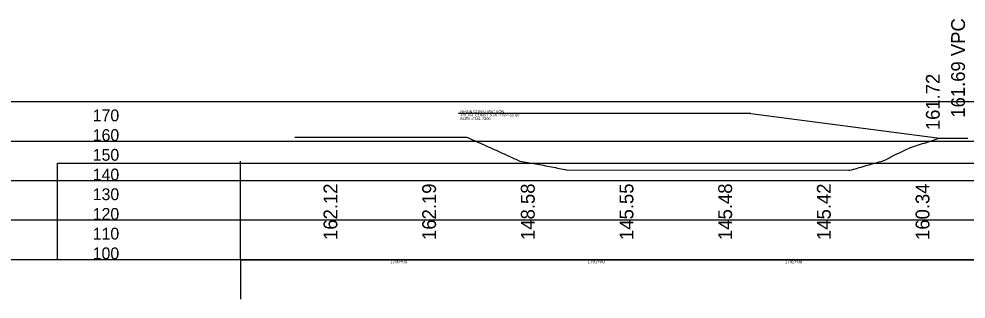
# Model space of a CAD drawing. Extents: x 2126510 to 2136144, y 865066 to 868066.
# Drawn here: x 2127256.4 to 2127736.3, y 866593.9 to 866736 of the extents above; entities that cross this region are included whole.
import ezdxf

# ---------------------------------------------------------------- set-up
doc = ezdxf.new("R2010")
doc.units = 0
for name, color, linetype in [('RD_EX_GuardRail', 7, 'Continuous'), ('RD_EX_H2O', 7, 'Continuous'), ('RD_EX_Misc', 7, 'Continuous')]:
    doc.layers.add(name, color=color, linetype=linetype)

msp = doc.modelspace()

# ---------------------------------------------------------------- linework, layer by layer
at = {"layer": 'RD_EX_GuardRail'}
for p, q in [((2131097.7, 866693.9), (2126517.45, 866693.9)), ((2128999.96, 866673.9), (2126517.45, 866673.9)), ((2131097.7, 866653.9), (2126517.45, 866653.9)), ((2131097.7, 866633.9), (2126517.45, 866633.9)), ((2131097.7, 866613.9), (2126517.45, 866613.9))]:
    msp.add_line(p, q, dxfattribs=at)
at = {"layer": 'RD_EX_H2O'}
for points in [[(2127396.19, 866675.97), (2127397.19, 866675.97), (2127398.19, 866675.97), (2127399.19, 866675.97), (2127400.19, 866675.97), (2127401.19, 866675.97), (2127402.19, 866675.97), (2127403.19, 866675.97), (2127404.19, 866675.97), (2127405.19, 866675.97), (2127406.19, 866675.97), (2127407.19, 866675.97), (2127408.19, 866675.98), (2127409.19, 866675.98), (2127410.19, 866675.99), (2127411.19, 866675.99), (2127412.19, 866676), (2127413.19, 866676), (2127414.19, 866676.01), (2127415.19, 866676.01), (2127416.19, 866676.02), (2127417.19, 866676.02), (2127418.19, 866676.02), (2127419.19, 866676.03), (2127420.19, 866676.03), (2127421.19, 866676.04), (2127422.19, 866676.04), (2127423.19, 866676.05), (2127424.19, 866676.05), (2127425.19, 866676.05), (2127426.19, 866676.05), (2127427.19, 866676.04), (2127428.19, 866676.04), (2127429.19, 866676.04), (2127430.19, 866676.04), (2127431.19, 866676.04), (2127432.19, 866676.04), (2127433.19, 866676.04), (2127434.19, 866676.04), (2127435.19, 866676.04), (2127436.19, 866676.04), (2127437.19, 866676.04), (2127438.19, 866676.04), (2127439.19, 866676.04), (2127440.19, 866676.04), (2127441.19, 866676.04), (2127442.19, 866676.04), (2127443.19, 866676.05), (2127444.19, 866676.05), (2127445.19, 866676.05), (2127446.19, 866676.05), (2127447.19, 866676.05), (2127448.19, 866676.05), (2127449.19, 866676.06), (2127450.19, 866676.06), (2127451.19, 866676.06), (2127452.19, 866676.06), (2127453.19, 866676.06), (2127454.19, 866676.06), (2127455.19, 866676.06), (2127456.19, 866676.06), (2127457.19, 866676.06), (2127458.19, 866676.06), (2127459.19, 866676.06), (2127460.19, 866676.06), (2127461.19, 866676.07), (2127462.19, 866676.07), (2127463.19, 866676.07), (2127464.19, 866676.08), (2127465.19, 866676.08), (2127466.19, 866676.09), (2127467.19, 866676.09), (2127468.19, 866676.09), (2127469.19, 866676.09), (2127470.19, 866676.09), (2127471.19, 866676.09), (2127472.19, 866676.1), (2127473.19, 866676.1), (2127474.19, 866676.1), (2127475.19, 866676.1), (2127476.19, 866676.1), (2127477.19, 866676.1), (2127478.19, 866676.1), (2127479.19, 866676.11), (2127480.19, 866676.11), (2127481.19, 866676.11), (2127482.19, 866676.11), (2127483.19, 866676.1), (2127484.19, 866675.65), (2127485.19, 866675.21), (2127486.19, 866674.76), (2127487.19, 866674.31), (2127488.19, 866673.87), (2127489.19, 866673.42), (2127490.19, 866672.98), (2127491.19, 866672.53), (2127492.19, 866672.09), (2127493.19, 866671.64), (2127494.19, 866671.19), (2127495.19, 866670.74), (2127496.19, 866670.29)], [(2127496.19, 866670.29), (2127497.19, 866669.84), (2127498.19, 866669.39), (2127499.19, 866668.93), (2127500.19, 866668.46), (2127501.19, 866668), (2127502.19, 866667.54), (2127503.19, 866667.08), (2127504.19, 866666.63), (2127505.19, 866666.18), (2127506.19, 866665.72), (2127507.19, 866665.27), (2127508.19, 866664.81), (2127509.19, 866664.36), (2127510.19, 866663.93), (2127511.19, 866663.75), (2127512.19, 866663.58), (2127513.19, 866663.4), (2127514.19, 866663.23), (2127515.19, 866663.05), (2127516.19, 866662.88), (2127517.19, 866662.72), (2127518.19, 866662.56), (2127519.19, 866662.41), (2127520.19, 866662.15), (2127521.19, 866661.95), (2127522.19, 866661.77), (2127523.19, 866661.59), (2127524.19, 866661.39), (2127525.19, 866661.19), (2127526.19, 866660.99), (2127527.19, 866660.79), (2127528.19, 866660.6), (2127529.19, 866660.4), (2127530.19, 866660.2), (2127531.19, 866660), (2127532.19, 866659.8), (2127533.19, 866659.61), (2127533.72, 866659.5), (2127676.64, 866659.31), (2127677.19, 866659.37), (2127678.19, 866659.52), (2127679.19, 866659.74), (2127680.19, 866660.03), (2127681.19, 866660.31), (2127682.19, 866660.6), (2127683.19, 866660.89), (2127684.19, 866661.18), (2127685.19, 866661.47), (2127686.19, 866661.76), (2127687.19, 866662.05), (2127688.19, 866662.33), (2127689.19, 866662.62), (2127690.19, 866662.91), (2127691.19, 866663.28), (2127692.19, 866663.53), (2127693.19, 866663.78), (2127694.19, 866664.03), (2127695.19, 866664.41), (2127696.19, 866664.94), (2127697.19, 866665.48), (2127698.19, 866666.02), (2127699.19, 866666.55), (2127700.19, 866667.04), (2127701.19, 866667.51), (2127702.19, 866667.99), (2127703.19, 866668.46), (2127704.19, 866668.94), (2127705.19, 866669.41), (2127706.19, 866669.89), (2127707.19, 866670.36), (2127708.19, 866670.82), (2127709.19, 866671.15), (2127710.19, 866671.47), (2127711.19, 866671.8), (2127712.19, 866672.12), (2127713.19, 866672.44), (2127714.19, 866672.77), (2127715.19, 866673.09), (2127716.19, 866673.42), (2127717.19, 866673.74), (2127718.19, 866674.07), (2127719.19, 866674.39), (2127720.19, 866674.72), (2127721.19, 866675.04), (2127722.19, 866675.37), (2127723.19, 866675.59), (2127724.19, 866675.59), (2127725.19, 866675.59), (2127726.19, 866675.59), (2127727.19, 866675.59), (2127728.19, 866675.59), (2127729.19, 866675.59), (2127730.19, 866675.59), (2127731.19, 866675.59), (2127732.19, 866675.58), (2127733.19, 866675.58), (2127734.19, 866675.58), (2127735.19, 866675.58), (2127736.19, 866675.58), (2127737.19, 866675.58)]]:
    msp.add_lwpolyline(points, dxfattribs=at)
at = {"layer": 'RD_EX_Misc'}
for p, q in [((2127627.25, 866688.14), (2127479.11, 866688.14)), ((2127722.94, 866675.62), (2127736.73, 866675.59)), ((2127368.72, 866613.9), (2127368.72, 866663.9)), ((2127368.72, 866613.9), (2131522.97, 866613.9)), ((2127368.72, 866613.9), (2127368.72, 866593.9))]:
    msp.add_line(p, q, dxfattribs=at)
for points in [[(2127627.25, 866688.14), (2127722.94, 866675.62)], [(2127275.85, 866613.9), (2127275.85, 866662.9), (2131989.68, 866662.9)]]:
    msp.add_lwpolyline(points, dxfattribs=at)

# ---------------------------------------------------------------- texts
for s, p in [('161.69 VPC', (2127735.73, 866685.92)), ('161.72', (2127722.94, 866679.62)), ('162.12', (2127417.72, 866623.9)), ('162.19', (2127467.72, 866623.9)), ('148.58', (2127517.72, 866623.9)), ('145.55', (2127567.72, 866623.9)), ('145.48', (2127617.72, 866623.9)), ('145.42', (2127667.72, 866623.9)), ('160.34', (2127717.72, 866623.9))]:
    msp.add_text(s, height=7, rotation=90, dxfattribs=at).set_placement(p)
for s, height, p in [('170', 6, (2127293.79, 866684.1)), ('BEGIN CONSTRUCTION', 1.4, (2127480.11, 866688.34)), ('I20_EB_CONST STA. 1792+55.00', 1.4, (2127480.11, 866686.54)), ('ELEV = 161.7200', 1.4, (2127480.11, 866684.74)), ('160', 6, (2127293.79, 866674.1)), ('150', 6, (2127293.79, 866664.1)), ('140', 6, (2127293.79, 866654.1)), ('130', 6, (2127293.79, 866644.1)), ('120', 6, (2127293.79, 866634.1)), ('110', 6, (2127293.79, 866624.1)), ('100', 6, (2127293.79, 866614.1)), ('I20', 0.0417, (2127368.72, 866614.78)), ('I20_EB_CONST', 0.0417, (2127368.72, 866614.65)), ('178900.000000', 0.0417, (2127368.72, 866614.53)), ('100', 0.0417, (2127368.72, 866614.4)), ('50', 0.0417, (2127368.72, 866614.28)), ('10', 0.0417, (2127368.72, 866614.15)), ('NOGAP', 0.0417, (2127368.72, 866614.03)), ('1790+00', 1.6, (2127444.51, 866612.1)), ('1791+00', 1.6, (2127544.51, 866612.1)), ('1792+00', 1.6, (2127644.51, 866612.1))]:
    msp.add_text(s, height=height, dxfattribs=at).set_placement(p)

doc.saveas('drawing.dxf')
